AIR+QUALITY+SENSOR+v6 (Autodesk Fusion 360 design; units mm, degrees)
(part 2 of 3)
sketch "Sketch29" plane through (0, 1.3, 0) normal (0, 1, 0) x axis (-1, 0, 0)
  line L1 (13.75, -36.3) -> (13.75, 21.15)
  line L2 (15, -36.3) -> (13.75, -36.3)
  line L3 (23.8, 34.5) -> (23.8, -27.5)
  line L4 (18, 36.3) -> (22, 36.3)
  line L5 (18, 32.55) -> (18, 36.3)
  line L6 (13, 32.55) -> (18, 32.55)
  line L7 (13, 36.3) -> (13, 32.55)
  line L8 (-13, 36.3) -> (13, 36.3)
  line L9 (-13, 32.55) -> (-13, 36.3)
  line L10 (-18, 32.55) -> (-13, 32.55)
  line L11 (-18, 36.3) -> (-18, 32.55)
  line L12 (-22, 36.3) -> (-18, 36.3)
  line L13 (-23.8, -27.5) -> (-23.8, 34.5)
  line L14 (-13.75, -36.3) -> (-15, -36.3)
  line L15 (-13.75, 21.15) -> (-13.75, -36.3)
  line L16 (11.75, 23.15) -> (-11.75, 23.15)
  line L17 (-6, 25.9667) -> (6, 25.9667)
  line L18 (-6, 20.3333) -> (-6, 25.9667)
  line L19 (6, 20.3333) -> (-6, 20.3333)
  line L20 (6, 25.9667) -> (6, 20.3333)
  line L21 (-6, 20.3333) -> (6, 25.9667)
  line L22 (6, 20.3333) -> (-6, 25.9667)
  line L23 (-4, 25.9667) -> (4, 25.9667)
  line L24 (-4, 20.3333) -> (-4, 25.9667)
  line L25 (4, 20.3333) -> (-4, 20.3333)
  line L26 (4, 25.9667) -> (4, 20.3333)
  line L27 (-4, 20.3333) -> (4, 25.9667)
  line L28 (4, 20.3333) -> (-4, 25.9667)
  arc A1 centre (15, -27.5) radius 8.8 clockwise from (23.8, -27.5) to (15, -36.3)
  arc A2 centre (22, 34.5) radius 1.8 clockwise from (22, 36.3) to (23.8, 34.5)
  arc A3 centre (-22, 34.5) radius 1.8 clockwise from (-23.8, 34.5) to (-22, 36.3)
  arc A4 centre (-15, -27.5) radius 8.8 clockwise from (-15, -36.3) to (-23.8, -27.5)
  arc A5 centre (-11.75, 21.15) radius 2 clockwise from (-13.75, 21.15) to (-11.75, 23.15)
  arc A6 centre (11.75, 21.15) radius 2 clockwise from (11.75, 23.15) to (13.75, 21.15)
  point P34 (0, 23.15)
  point P39 (0, 23.15)
  point P35 (4, 25.9667)
  point P32 (-6, 20.3333)
  point P33 (6, 20.3333)
  horizontal L17
  perpendicular L17 L18
  parallel L17 L19
  parallel L18 L20
  coincident L21 P34
  coincident L22 P34
  midpoint L16 P34
  horizontal L23
  perpendicular L23 L24
  parallel L23 L25
  parallel L24 L26
  coincident L27 P39
  coincident L28 P39
  coincident L17 P35
  coincident P34 P39
  dimension "d189" distance P32 P33 = 12
  dimension "d190" distance L20 L26 = 2
extrude "Extrude35" new body sketch "Sketch29" profile of L16 L17 L18 L20 L24 L26 along normal blind 7
move_face "MoveFace16"
sketch "Sketch30" plane through (0, 0, 39.5) normal (0, 0, 1) x axis (-1, 0, 0)
  line L1 (10.8759, -1.8) -> (22, -1.8)
  line L2 (10.8759, -6.5) -> (10.8759, -1.8)
  curve K1 (10.2532, -7) -> (10.8759, -6.5)
  line L3 (9.0455, -7) -> (10.2532, -7)
  curve K2 (8.4566, -6.5) -> (9.0455, -7)
  line L4 (8.4566, -1.8) -> (8.4566, -6.5)
  line L5 (2.4622, -1.8) -> (8.4566, -1.8)
  line L6 (-22, -1.8) -> (-10.4622, -1.8)
  line L7 (-22, -25) -> (-22, -1.8)
  line L8 (22, -25) -> (-22, -25)
  line L9 (22, -1.8) -> (22, -25)
  line L10 (6.5, -12.5) -> (-4, -12.5)
  line L11 (-14.5, -12.5) -> (-4, -12.5)
  line L12 (-14.5, -26.2029) -> (-14.5, -12.5)
  line L13 (6.5, -27.3065) -> (6.5, -12.5)
  circle C1 centre (-4, -12.5) radius 10.5
  arc A1 centre (-4, -12.5) radius 12.5 clockwise from (-10.4622, -1.8) to (2.4622, -1.8)
  point P2 (-4, -12.5)
  point P15 (-4, -12.5)
  point P16 (6.5, -12.5)
  point P17 (-4, -12.5)
  point P18 (-14.5, -12.5)
  coincident P2 P15
  coincident C1 P16
  horizontal L10
  coincident P2 P17
  coincident C1 P18
  parallel L10 L11
  tangent C1 L12
  tangent C1 L13
extrude "Extrude36" cut sketch "Sketch30" profile of C1 L8 L12 L13 against normal blind 1.2
sketch "Sketch31" plane through (0, 1.3, 0) normal (0, 1, 0) x axis (-1, 0, 0)
  line L1 (13.75, -36.3) -> (13.75, 21.15)
  line L2 (15, -36.3) -> (13.75, -36.3)
  line L3 (23.8, 34.5) -> (23.8, -27.5)
  line L4 (18, 36.3) -> (22, 36.3)
  line L5 (18, 32.55) -> (18, 36.3)
  line L6 (13, 32.55) -> (18, 32.55)
  line L7 (13, 36.3) -> (13, 32.55)
  line L8 (-13, 36.3) -> (13, 36.3)
  line L9 (-13, 32.55) -> (-13, 36.3)
  line L10 (-18, 32.55) -> (-13, 32.55)
  line L11 (-18, 36.3) -> (-18, 32.55)
  line L12 (-22, 36.3) -> (-18, 36.3)
  line L13 (-23.8, -27.5) -> (-23.8, 34.5)
  line L14 (-13.75, -36.3) -> (-15, -36.3)
  line L15 (-13.75, 21.15) -> (-13.75, -36.3)
  line L16 (11.75, 23.15) -> (-11.75, 23.15)
  line L17 (16.2, 32.55) -> (16.2, 35.025)
  line L18 (18, 32.55) -> (16.2, 32.55)
  line L19 (18, 38.3) -> (18, 32.55)
  line L20 (14.2, 38.3) -> (18, 38.3)
  line L21 (14.2, 35.025) -> (14.2, 38.3)
  line L22 (16.2, 35.025) -> (14.2, 35.025)
  line L23 (14.2, 35.025) -> (16.2, 35.025)
  line L24 (14.2, 37.5) -> (14.2, 35.025)
  line L25 (13, 37.5) -> (14.2, 37.5)
  line L26 (13, 32.55) -> (13, 37.5)
  line L27 (16.2, 32.55) -> (13, 32.55)
  line L28 (16.2, 35.025) -> (16.2, 32.55)
  line L29 (-14.5, 38.3) -> (-14.5, 35.025)
  line L30 (-18, 38.3) -> (-14.5, 38.3)
  line L31 (-18, 32.55) -> (-18, 38.3)
  line L32 (-16.2, 32.55) -> (-18, 32.55)
  line L33 (-16.2, 35.025) -> (-16.2, 32.55)
  line L34 (-14.5, 35.025) -> (-16.2, 35.025)
  line L35 (-16, 34.6) -> (16, 34.6)
  line L36 (-16, 33.5) -> (-16, 34.6)
  line L37 (16, 33.5) -> (-16, 33.5)
  line L38 (16, 34.6) -> (16, 33.5)
  line L39 (10.4443, 34.05) -> (16, 34.05)
  line L40 (16.2, 33.075) -> (14.2, 33.075)
  line L41 (18, 33.075) -> (14.2, 33.075)
  line L42 (18, 31.075) -> (18, 33.075)
  line L43 (14.2, 31.075) -> (18, 31.075)
  line L44 (14.2, 33.075) -> (14.2, 31.075)
  arc A1 centre (15, -27.5) radius 8.8 clockwise from (23.8, -27.5) to (15, -36.3)
  arc A2 centre (22, 34.5) radius 1.8 clockwise from (22, 36.3) to (23.8, 34.5)
  arc A3 centre (-22, 34.5) radius 1.8 clockwise from (-23.8, 34.5) to (-22, 36.3)
  arc A4 centre (-15, -27.5) radius 8.8 clockwise from (-15, -36.3) to (-23.8, -27.5)
  arc A5 centre (-11.75, 21.15) radius 2 clockwise from (-13.75, 21.15) to (-11.75, 23.15)
  arc A6 centre (11.75, 21.15) radius 2 clockwise from (11.75, 23.15) to (13.75, 21.15)
  point P52 (16, 34.05)
  point P30 (16.2, 35.025)
  point P55 (16.2, 33.075)
  point P35 (14.2, 35.025)
  point P54 (14.2, 33.075)
  point P58 (14.2, 31.075)
  midpoint L38 P52
  horizontal L39
  symmetric P30 L39 P55
  symmetric P35 L39 P54
  horizontal L41
  vertical L42
  horizontal L43
  vertical L44
  dimension "d195" distance P54 P58 = 2
extrude "Extrude37" new body sketch "Sketch31" profile of L5 L6 L17 L18 L19 L27 L28 L40 L41 L42 L43 L44 along normal blind 21.2
mirror "Mirror3" mirrorStitchTolerance 0.1
move_face "MoveFace17"
combine "Combine11"
move_face "MoveFace18"
combine "Combine12"
move_face "MoveFace19"
remove_body "RemoveBody17"
sketch "Sketch32" plane through (0, 0, 38.1) normal (0, 0, 1) x axis (-1, 0, 0)
  line L1 (22, -25) -> (-22, -25)
  line L2 (22, -21) -> (22, -25)
  line L3 (-22, -21) -> (22, -21)
  line L4 (-22, -25) -> (-22, -21)
  line L5 (-14.5, -12.5) -> (-14.5, -25)
  line L6 (6.5, -25) -> (6.5, -12.5)
  line L7 (22, -25) -> (6.5, -25)
  line L8 (22, -1.8) -> (22, -25)
  line L9 (10.8759, -1.8) -> (22, -1.8)
  line L10 (10.8759, -6.5) -> (10.8759, -1.8)
  curve K1 (10.2532, -7) -> (10.8759, -6.5)
  line L11 (9.0455, -7) -> (10.2532, -7)
  curve K2 (8.4566, -6.5) -> (9.0455, -7)
  line L12 (8.4566, -1.8) -> (8.4566, -6.5)
  line L13 (2.4622, -1.8) -> (8.4566, -1.8)
  line L14 (-22, -1.8) -> (-10.4622, -1.8)
  line L15 (-22, -25) -> (-22, -1.8)
  line L16 (-14.5, -25) -> (-22, -25)
  arc A1 centre (-4, -12.5) radius 10.5 clockwise from (-14.5, -12.5) to (6.5, -12.5)
  arc A2 centre (-4, -12.5) radius 12.5 clockwise from (-10.4622, -1.8) to (2.4622, -1.8)
  circle C1 centre (-4, -12.5) radius 10.5
  point P7 (-14.5, -12.5)
  concentric A1 C1
  coincident P7 C1
extrude "Extrude38" new body sketch "Sketch32" profile of L1 L3 L5 L6 C1 against normal blind 1.5
fillet "Fillet7" radius 0.5
move_face "MoveFace20"
combine "Combine13"
delete_face "DeleteFace20"
move_face "MoveFace21"
split "Split2"
extrude "Extrude39" cut of existing geometry blind -1.5
extrude "Extrude40" cut of existing geometry blind -1.5
split "Split3"
split "Split4"
move_face "MoveFace22"
move_face "MoveFace23"
combine "Combine14"
delete_face "DeleteFace21"
delete_face "DeleteFace22"
sketch "Sketch33" plane through (0, -0.2, 0) normal (0, -1, 0) x axis (1, 0, 0)
  line L1 (-22, 37.5) -> (22, 37.5)
  line L2 (-25, -27.5) -> (-25, 34.5)
  line L3 (15, -37.5) -> (-15, -37.5)
  line L4 (25, 34.5) -> (25, -27.5)
  line L5 (-35.7104, 55.4052) -> (-22, 34.5)
  line L6 (-39.8914, 52.6631) -> (-35.7104, 55.4052)
  line L7 (-31.5293, 58.1472) -> (-35.7104, 55.4052)
  line L8 (-10, 37.5) -> (-22, 37.5)
  line L9 (-25, 19.5) -> (-25, 34.5)
  line L10 (-25, 19.5) -> (-39.8914, 52.6631)
  line L11 (-10, 37.5) -> (-31.5293, 58.1472)
  line L12 (-31.8817, 54.3285) -> (-34.0651, 52.8965)
  line L13 (-17.4624, 40.5) -> (-31.8817, 54.3285)
  line L14 (-17.4624, 40.5) -> (-22, 40.5)
  line L15 (-36.1065, 51.5577) -> (-34.0651, 52.8965)
  line L16 (-28, 33.5046) -> (-36.1065, 51.5577)
  line L17 (-28, 33.5046) -> (-28, 34.5)
  line L18 (15, -40.5) -> (-15, -40.5)
  line L19 (28, 34.5) -> (28, -27.5)
  line L20 (-22, 40.5) -> (22, 40.5)
  line L21 (-28, -27.5) -> (-28, 34.5)
  arc A1 centre (-22, 34.5) radius 3 clockwise from (-25, 34.5) to (-22, 37.5)
  arc A2 centre (-15, -27.5) radius 10 clockwise from (-15, -37.5) to (-25, -27.5)
  arc A3 centre (15, -27.5) radius 10 clockwise from (25, -27.5) to (15, -37.5)
  arc A4 centre (22, 34.5) radius 3 clockwise from (22, 37.5) to (25, 34.5)
  arc A5 centre (-15, -27.5) radius 13 clockwise from (-15, -40.5) to (-28, -27.5)
  arc A6 centre (15, -27.5) radius 13 clockwise from (28, -27.5) to (15, -40.5)
  arc A7 centre (22, 34.5) radius 6 clockwise from (22, 40.5) to (28, 34.5)
  arc A8 centre (-22, 34.5) radius 6 clockwise from (-28, 34.5) to (-22, 40.5)
  point P5 (-22, 34.5)
  point P14 (-22, 34.5)
  point P3 (-22, 37.5)
  point P18 (-22, 37.5)
  point P4 (-25, 34.5)
  point P20 (-25, 34.5)
  point P15 (-35.7104, 55.4052)
  point P16 (-39.8914, 52.6631)
  point P17 (-31.5293, 58.1472)
  point P19 (-10, 37.5)
  point P21 (-25, 19.5)
  coincident P5 P14
  perpendicular L5 L6
  perpendicular L5 L7
  coincident P3 P18
  parallel L1 L8
  coincident P4 P20
  parallel L2 L9
  dimension "d208" distance P14 P15 = 25
  dimension "d209" distance P15 P16 = 5
  dimension "d210" distance P15 P17 = 5
  dimension "d211" distance P18 P19 = 12
  dimension "d212" distance P20 P21 = 15
  dimension "d213" = 3
  dimension "d214" = -3
  dimension "d215" = 3
extrude "Extrude41" new body sketch "Sketch33" profile of L1 A1 L2 L5 L6 L7 L8 L9 L10 L11 L12 L13 L14 L15 L16 L17 A8 L20 L21 against normal blind 4
offset_faces "OffsetFaces10" distance -0.5
fillet "Fillet8" radius 2.5
combine "Combine15"
offset_faces "OffsetFaces11" distance -0.5
fillet "Fillet9" radius 1.25
fillet "Fillet10" radius 5
sketch "Sketch34" plane through (0, 31, 0) normal (0, 1, 0) x axis (-1, 0, 0)
  line L1 (-1.5, -10.5) -> (-14.5, -10.5)
  line L2 (-1.5, -30.5) -> (-1.5, -10.5)
  line L3 (-14.5, -30.5) -> (-1.5, -30.5)
  line L4 (-14.5, -10.5) -> (-14.5, -30.5)
  line L5 (-14.975, -30.405) -> (-14.975, -10.595)
  line L6 (-1.025, -30.405) -> (-14.975, -30.405)
  line L7 (-1.025, -10.595) -> (-1.025, -30.405)
  line L8 (-14.975, -10.595) -> (-1.025, -10.595)
  line L9 (-12.2, -27.65) -> (-3.8, -27.65)
  curve K1 (-12.2, -27.65) -> (-12.9, -26.8848)
  line L10 (-12.9, -17.1081) -> (-12.9, -26.8848)
  curve K2 (-12.9, -17.1081) -> (-12.2, -13.35)
  line L11 (-3.8, -13.35) -> (-12.2, -13.35)
  curve K3 (-3.8, -13.35) -> (-3.1, -17.1081)
  line L12 (-3.1, -26.8848) -> (-3.1, -17.1081)
  curve K4 (-3.1, -26.8848) -> (-3.8, -27.65)
  line L13 (0.575, -32.005) -> (-16.575, -32.005)
  line L14 (0.575, -8.995) -> (0.575, -32.005)
  line L15 (-16.575, -8.995) -> (0.575, -8.995)
  line L16 (-16.575, -32.005) -> (-16.575, -8.995)
  circle C1 centre (-8, -20.5) radius 15.3744
  dimension "d226" = 1.6
extrude "Extrude42" add sketch "Sketch34" profile of C1 L15 L13 L14 L16 along normal blind 2
delete_face "DeleteFace23"
offset_faces "OffsetFaces12" distance 0.5
fillet "Fillet11" radius 1
delete_face "DeleteFace24"
position "Position15"
sketch "Sketch35" plane through (27, 0, 0) normal (1, 0, 0) x axis (0, 1, 0)
  line L1 (22.4, -17.1667) -> (22.4, -13.1667)
  line L2 (4.4, -17.1667) -> (22.4, -17.1667)
  line L3 (4.4, -13.1667) -> (4.4, -17.1667)
  line L4 (22.4, -13.1667) -> (4.4, -13.1667)
  line L5 (22.4, -26.5) -> (22.4, -22.5)
  line L6 (4.4, -26.5) -> (22.4, -26.5)
  line L7 (4.4, -22.5) -> (4.4, -26.5)
  line L8 (22.4, -22.5) -> (4.4, -22.5)
  line L9 (22.4, -7.8333) -> (22.4, -3.8333)
  line L10 (4.4, -7.8333) -> (22.4, -7.8333)
  line L11 (4.4, -3.8333) -> (4.4, -7.8333)
  line L12 (22.4, -3.8333) -> (4.4, -3.8333)
  line L13 (1.8, -27.5) -> (1.8, 34.5)
  line L14 (25, -27.5) -> (1.8, -27.5)
  line L15 (25, 34.5) -> (25, -27.5)
  line L16 (1.8, 34.5) -> (25, 34.5)
  line L17 (7.175, 6.595) -> (7.175, 26.405)
  line L18 (21.125, 6.595) -> (7.175, 6.595)
  line L19 (21.125, 26.405) -> (21.125, 6.595)
  line L20 (7.175, 26.405) -> (21.125, 26.405)
  line L21 (9.95, 9.35) -> (18.35, 9.35)
  curve K1 (9.95, 9.35) -> (9.25, 10.1152)
  line L22 (9.25, 19.8919) -> (9.25, 10.1152)
  curve K2 (9.25, 19.8919) -> (9.95, 23.65)
  line L23 (18.35, 23.65) -> (9.95, 23.65)
  curve K3 (18.35, 23.65) -> (19.05, 19.8919)
  line L24 (19.05, 10.1152) -> (19.05, 19.8919)
  curve K4 (19.05, 10.1152) -> (18.35, 9.35)
  line L25 (21.125, 6.595) -> (7.175, 26.405)
  line L26 (3.3, 32) -> (25, 32)
  line L27 (3.3, 1) -> (3.3, 32)
  line L28 (25, 1) -> (3.3, 1)
  line L29 (25, 32) -> (25, 1)
  line L30 (3.3, 1) -> (25, 32)
  line L31 (25, 1) -> (3.3, 32)
  point P18 (7.175, 26.405)
  point P30 (7.175, 26.405)
  point P20 (21.125, 6.595)
  point P31 (21.125, 6.595)
  point P36 (14.15, 16.5)
  point P33 (3.3, 32)
  point P34 (3.3, 1)
  coincident P18 P30
  coincident P20 P31
  horizontal L26
  perpendicular L26 L27
  parallel L26 L28
  parallel L27 L29
  coincident L30 P36
  coincident L31 P36
  midpoint L25 P36
  dimension "d232" distance P33 P34 = 31
extrude "Extrude43" new body sketch "Sketch35" profile of L15 L17 L18 L19 L20 L21 K1 L22 K2 L23 K3 L24 K4 L25 L26 L27 L28 L29 along normal blind 5.7
offset_faces "OffsetFaces13" distance -2
draft "Draft3" Angle1 30 Angle2 0
shell "Shell4" innerThickness 1.2
extrude "Extrude44" cut of existing geometry blind -6
combine "Combine16"
delete_face "DeleteFace25"
extrude "Extrude45" cut of existing geometry blind -2
move_face "MoveFace24"
position "Position16"
sketch "Sketch36" plane through (32.7, 0, 0) normal (1, 0, 0) x axis (0, 1, 0)
  line L1 (25, 30) -> (25, 3)
  line L2 (5.3, 30) -> (25, 30)
  line L3 (5.3, 3) -> (5.3, 30)
  line L4 (25, 3) -> (5.3, 3)
  line L5 (8.175, 6.595) -> (8.175, 26.405)
  line L6 (22.125, 26.405) -> (22.125, 6.595)
  line L7 (10.95, 9.35) -> (19.35, 9.35)
  curve K1 (10.95, 9.35) -> (10.25, 10.1152)
  line L8 (10.25, 19.8919) -> (10.25, 10.1152)
  curve K2 (10.25, 19.8919) -> (10.95, 23.65)
  line L9 (19.35, 23.65) -> (10.95, 23.65)
  curve K3 (19.35, 23.65) -> (20.05, 19.8919)
  line L10 (20.05, 10.1152) -> (20.05, 19.8919)
  curve K4 (20.05, 10.1152) -> (19.35, 9.35)
  line L11 (22.125, 6.595) -> (8.175, 26.405)
  line L12 (8.65, 26.5) -> (21.65, 26.5)
  line L13 (8.65, 6.5) -> (8.65, 26.5)
  line L14 (21.65, 6.5) -> (8.65, 6.5)
  line L15 (21.65, 26.5) -> (21.65, 6.5)
  line L16 (8.65, 6.5) -> (21.65, 26.5)
  line L17 (21.65, 6.5) -> (8.65, 26.5)
  point P6 (8.175, 26.405)
  point P18 (8.175, 26.405)
  point P8 (22.125, 6.595)
  point P19 (22.125, 6.595)
  point P24 (15.15, 16.5)
  point P22 (8.65, 6.5)
  point P23 (21.65, 6.5)
  point P21 (8.65, 26.5)
  coincident P6 P18
  coincident P8 P19
  horizontal L12
  perpendicular L12 L13
  parallel L12 L14
  parallel L13 L15
  coincident L16 P24
  coincident L17 P24
  midpoint L11 P24
  dimension "d243" distance P22 P23 = 13
  dimension "d244" distance P21 P22 = 20
extrude "Extrude46" cut sketch "Sketch36" profile of L7 K1 L8 K2 L9 K3 L10 K4 L11 L12 L13 L14 L15 against normal blind 1.2
extrude "Extrude47" cut of existing geometry blind -7
sketch "Sketch37" plane through (0, 27, 0) normal (0, 1, 0) x axis (-1, 0, 0)
  line L1 (-13.5, -2.6142) -> (13.5, -2.6142)
  line L2 (-23.2642, 26.15) -> (-23.2642, 7.15)
  line L3 (13.5, 35.9142) -> (-13.5, 35.9142)
  line L4 (23.2642, 7.15) -> (23.2642, 26.15)
  line L5 (27, 34.5) -> (27, -27.5)
  line L6 (-22, 39.5) -> (22, 39.5)
  line L7 (-27, -27.5) -> (-27, 34.5)
  line L8 (15, -39.5) -> (-15, -39.5)
  line L9 (-31.5, 26.5) -> (-32.7, 26.5)
  line L10 (-31.5, 29.3072) -> (-31.5, 26.5)
  line L11 (-27, 31.9053) -> (-31.5, 29.3072)
  line L12 (-25.8, 31.9053) -> (-27, 31.9053)
  line L13 (-25.8, 34.5) -> (-25.8, 31.9053)
  line L14 (-14.5, 38.3) -> (-22, 38.3)
  line L15 (-14.5, 39.5) -> (-14.5, 38.3)
  line L16 (-22, 39.5) -> (-14.5, 39.5)
  line L17 (-27, 33.2909) -> (-27, 34.5)
  line L18 (-32.7, 30) -> (-27, 33.2909)
  line L19 (-32.7, 26.5) -> (-32.7, 30)
  line L20 (-32.7, 6.5) -> (-31.5, 6.5)
  line L21 (-32.7, 3) -> (-32.7, 6.5)
  line L22 (-27, -0.2909) -> (-32.7, 3)
  line L23 (-27, -27.5) -> (-27, -0.2909)
  line L24 (15, -39.5) -> (-15, -39.5)
  line L25 (27, 34.5) -> (27, -27.5)
  line L26 (6.5, 39.5) -> (22, 39.5)
  line L27 (6.5, 38.3) -> (6.5, 39.5)
  line L28 (22, 38.3) -> (6.5, 38.3)
  line L29 (25.8, -27.5) -> (25.8, 34.5)
  line L30 (-15, -38.3) -> (15, -38.3)
  line L31 (-25.8, 1.0947) -> (-25.8, -27.5)
  line L32 (-27, 1.0947) -> (-25.8, 1.0947)
  line L33 (-31.5, 3.6928) -> (-27, 1.0947)
  line L34 (-31.5, 6.5) -> (-31.5, 3.6928)
  line L35 (-32.7, 6.5) -> (-32.7, 26.5)
  arc A1 centre (13.5, 7.15) radius 9.7642 clockwise from (23.2642, 7.15) to (13.5, -2.6142)
  arc A2 centre (-13.5, 7.15) radius 9.7642 clockwise from (-13.5, -2.6142) to (-23.2642, 7.15)
  arc A3 centre (-13.5, 26.15) radius 9.7642 clockwise from (-23.2642, 26.15) to (-13.5, 35.9142)
  arc A4 centre (13.5, 26.15) radius 9.7642 clockwise from (13.5, 35.9142) to (23.2642, 26.15)
  arc A5 centre (15, -27.5) radius 12 clockwise from (27, -27.5) to (15, -39.5)
  arc A6 centre (22, 34.5) radius 5 clockwise from (22, 39.5) to (27, 34.5)
  arc A7 centre (-22, 34.5) radius 5 clockwise from (-27, 34.5) to (-22, 39.5)
  arc A8 centre (-15, -27.5) radius 12 clockwise from (-15, -39.5) to (-27, -27.5)
  circle C1 centre (-8, -20.5) radius 16.9638
  arc A9 centre (-22, 34.5) radius 3.8 clockwise from (-25.8, 34.5) to (-22, 38.3)
  arc A10 centre (-22, 34.5) radius 5 clockwise from (-27, 34.5) to (-22, 39.5)
  arc A11 centre (-15, -27.5) radius 12 clockwise from (-15, -39.5) to (-27, -27.5)
  arc A12 centre (15, -27.5) radius 12 clockwise from (27, -27.5) to (15, -39.5)
  arc A13 centre (22, 34.5) radius 5 clockwise from (22, 39.5) to (27, 34.5)
  arc A14 centre (22, 34.5) radius 3.8 clockwise from (22, 38.3) to (25.8, 34.5)
  arc A15 centre (15, -27.5) radius 10.8 clockwise from (25.8, -27.5) to (15, -38.3)
  arc A16 centre (-15, -27.5) radius 10.8 clockwise from (-15, -38.3) to (-25.8, -27.5)
  point P27 (-32.7, 26.5)
  point P65 (-32.7, 26.5)
  point P42 (-32.7, 6.5)
  point P66 (-32.7, 6.5)
  coincident P27 P65
  coincident P42 P66
extrude "Extrude48" new body sketch "Sketch37" profile of L7 L9 L10 L11 L18 L19 L20 L21 L22 L33 L34 L35 against normal blind 2
sketch "Sketch38" plane through (0, 27, 0) normal (0, 1, 0) x axis (-1, 0, 0)
  line L1 (-32.7, 30) -> (-27, 33.2909)
  line L2 (-32.7, 3) -> (-32.7, 30)
  line L3 (-27, -0.2909) -> (-32.7, 3)
  line L4 (-27, 33.2909) -> (-27, -0.2909)
  line L5 (-32.7, 6.5) -> (-31.5, 6.5)
  line L6 (-32.7, 3) -> (-32.7, 6.5)
  line L7 (-27, -0.2909) -> (-32.7, 3)
  line L8 (-27, -27.5) -> (-27, -0.2909)
  line L9 (15, -39.5) -> (-15, -39.5)
  line L10 (27, 34.5) -> (27, -27.5)
  line L11 (6.5, 39.5) -> (22, 39.5)
  line L12 (6.5, 38.3) -> (6.5, 39.5)
  line L13 (22, 38.3) -> (6.5, 38.3)
  line L14 (25.8, -27.5) -> (25.8, 34.5)
  line L15 (-15, -38.3) -> (15, -38.3)
  line L16 (-25.8, 1.0947) -> (-25.8, -27.5)
  line L17 (-27, 1.0947) -> (-25.8, 1.0947)
  line L18 (-31.5, 3.6928) -> (-27, 1.0947)
  line L19 (-31.5, 6.5) -> (-31.5, 3.6928)
  line L20 (-31.5, 26.5) -> (-32.7, 26.5)
  line L21 (-31.5, 29.3072) -> (-31.5, 26.5)
  line L22 (-27, 31.9053) -> (-31.5, 29.3072)
  line L23 (-25.8, 31.9053) -> (-27, 31.9053)
  line L24 (-25.8, 34.5) -> (-25.8, 31.9053)
  line L25 (-14.5, 38.3) -> (-22, 38.3)
  line L26 (-14.5, 39.5) -> (-14.5, 38.3)
  line L27 (-22, 39.5) -> (-14.5, 39.5)
  line L28 (-27, 33.2909) -> (-27, 34.5)
  line L29 (-32.7, 30) -> (-27, 33.2909)
  line L30 (-32.7, 26.5) -> (-32.7, 30)
  line L31 (-31.5, 26.5) -> (-32.7, 26.5)
  line L32 (-31.5, 6.5) -> (-31.5, 26.5)
  line L33 (-32.7, 6.5) -> (-31.5, 6.5)
  line L34 (-32.7, 26.5) -> (-32.7, 6.5)
  arc A1 centre (-15, -27.5) radius 12 clockwise from (-15, -39.5) to (-27, -27.5)
  arc A2 centre (15, -27.5) radius 12 clockwise from (27, -27.5) to (15, -39.5)
  arc A3 centre (22, 34.5) radius 5 clockwise from (22, 39.5) to (27, 34.5)
  arc A4 centre (22, 34.5) radius 3.8 clockwise from (22, 38.3) to (25.8, 34.5)
  arc A5 centre (15, -27.5) radius 10.8 clockwise from (25.8, -27.5) to (15, -38.3)
  arc A6 centre (-15, -27.5) radius 10.8 clockwise from (-15, -38.3) to (-25.8, -27.5)
  arc A7 centre (-22, 34.5) radius 3.8 clockwise from (-25.8, 34.5) to (-22, 38.3)
  arc A8 centre (-22, 34.5) radius 5 clockwise from (-27, 34.5) to (-22, 39.5)
  point P6 (-31.5, 6.5)
  point P46 (-31.5, 6.5)
  point P30 (-32.7, 26.5)
  point P44 (-32.7, 26.5)
  horizontal L31
  vertical L32
  horizontal L33
  vertical L34
  coincident P6 P46
  coincident P30 P44
extrude "Extrude49" new body sketch "Sketch38" profile of L2 L5 L20 L31 L32 L33 L34 against normal blind 5
combine "Combine17"
sketch "Sketch39" plane through (0, 25, 0) normal (0, 1, 0) x axis (-1, 0, 0)
  line L1 (-32.7, 6.5) -> (-31.5, 6.5)
  line L2 (-32.7, 3) -> (-32.7, 6.5)
  line L3 (-27, -0.2909) -> (-32.7, 3)
  line L4 (-27, -27.5) -> (-27, -0.2909)
  line L5 (15, -39.5) -> (-15, -39.5)
  line L6 (27, 34.5) -> (27, -27.5)
  line L7 (6.5, 39.5) -> (22, 39.5)
  line L8 (6.5, 38.3) -> (6.5, 39.5)
  line L9 (22, 38.3) -> (6.5, 38.3)
  line L10 (25.8, -27.5) -> (25.8, 34.5)
  line L11 (-15, -38.3) -> (15, -38.3)
  line L12 (-25.8, 1.0947) -> (-25.8, -27.5)
  line L13 (-27, 1.0947) -> (-25.8, 1.0947)
  line L14 (-31.5, 3.6928) -> (-27, 1.0947)
  line L15 (-31.5, 6.5) -> (-31.5, 3.6928)
  line L16 (-31.5, 26.5) -> (-32.7, 26.5)
  line L17 (-31.5, 29.3072) -> (-31.5, 26.5)
  line L18 (-27, 31.9053) -> (-31.5, 29.3072)
  line L19 (-25.8, 31.9053) -> (-27, 31.9053)
  line L20 (-25.8, 34.5) -> (-25.8, 31.9053)
  line L21 (-14.5, 38.3) -> (-22, 38.3)
  line L22 (-14.5, 39.5) -> (-14.5, 38.3)
  line L23 (-22, 39.5) -> (-14.5, 39.5)
  line L24 (-27, 33.2909) -> (-27, 34.5)
  line L25 (-32.7, 30) -> (-27, 33.2909)
  line L26 (-32.7, 26.5) -> (-32.7, 30)
  line L27 (-31.3, 6.7) -> (-31.3, 3.8083)
  line L28 (-32.9, 6.7) -> (-31.3, 6.7)
  line L29 (-32.9, 2.8845) -> (-32.9, 6.7)
  line L30 (-27.2, -0.4064) -> (-32.9, 2.8845)
  line L31 (-27.2, -27.5) -> (-27.2, -0.4064)
  line L32 (15, -39.7) -> (-15, -39.7)
  line L33 (27.2, 34.5) -> (27.2, -27.5)
  line L34 (6.3, 39.7) -> (22, 39.7)
  line L35 (6.3, 38.1) -> (6.3, 39.7)
  line L36 (22, 38.1) -> (6.3, 38.1)
  line L37 (25.6, -27.5) -> (25.6, 34.5)
  line L38 (-15, -38.1) -> (15, -38.1)
  line L39 (-25.6, 1.2947) -> (-25.6, -27.5)
  line L40 (-26.9464, 1.2947) -> (-25.6, 1.2947)
  line L41 (-31.3, 3.8083) -> (-26.9464, 1.2947)
  line L42 (-25.6, 31.7053) -> (-26.9464, 31.7053)
  line L43 (-25.6, 34.5) -> (-25.6, 31.7053)
  line L44 (-14.3, 38.1) -> (-22, 38.1)
  line L45 (-14.3, 39.7) -> (-14.3, 38.1)
  line L46 (-22, 39.7) -> (-14.3, 39.7)
  line L47 (-27.2, 33.4064) -> (-27.2, 34.5)
  line L48 (-32.9, 30.1155) -> (-27.2, 33.4064)
  line L49 (-32.9, 26.3) -> (-32.9, 30.1155)
  line L50 (-31.3, 26.3) -> (-32.9, 26.3)
  line L51 (-31.3, 29.1917) -> (-31.3, 26.3)
  line L52 (-26.9464, 31.7053) -> (-31.3, 29.1917)
  line L53 (-34.4, 8.2) -> (-29.8, 8.2)
  line L54 (-34.4, 2.0185) -> (-34.4, 8.2)
  line L55 (-28.7, -1.2724) -> (-34.4, 2.0185)
  line L56 (-28.7, -27.5) -> (-28.7, -1.2724)
  line L57 (15, -41.2) -> (-15, -41.2)
  line L58 (28.7, 34.5) -> (28.7, -27.5)
  line L59 (4.8, 41.2) -> (22, 41.2)
  line L60 (4.8, 36.6) -> (4.8, 41.2)
  line L61 (22, 36.6) -> (4.8, 36.6)
  line L62 (24.1, -27.5) -> (24.1, 34.5)
  line L63 (-15, -36.6) -> (15, -36.6)
  line L64 (-24.1, 2.7947) -> (-24.1, -27.5)
  line L65 (-26.5445, 2.7947) -> (-24.1, 2.7947)
  line L66 (-29.8, 4.6743) -> (-26.5445, 2.7947)
  line L67 (-29.8, 8.2) -> (-29.8, 4.6743)
  line L68 (-24.1, 34.5) -> (-24.1, 30.2053)
  line L69 (-12.8, 36.6) -> (-22, 36.6)
  line L70 (-12.8, 41.2) -> (-12.8, 36.6)
  line L71 (-22, 41.2) -> (-12.8, 41.2)
  line L72 (-28.7, 34.2724) -> (-28.7, 34.5)
  line L73 (-34.4, 30.9815) -> (-28.7, 34.2724)
  line L74 (-34.4, 24.8) -> (-34.4, 30.9815)
  line L75 (-29.8, 24.8) -> (-34.4, 24.8)
  line L76 (-29.8, 28.3257) -> (-29.8, 24.8)
  line L77 (-26.5445, 30.2053) -> (-29.8, 28.3257)
  line L78 (-24.1, 30.2053) -> (-26.5445, 30.2053)
  line L79 (-29.8, 24.8) -> (-29.8, 8.2)
  line L80 (-32.7, 6.5) -> (-31.5, 6.5)
  line L81 (-32.7, 26.5) -> (-32.7, 6.5)
  line L82 (-31.5, 26.5) -> (-32.7, 26.5)
  line L83 (-31.5, 6.5) -> (-31.5, 26.5)
  line L84 (-24.1, 31.7053) -> (-25.6, 31.7053)
  line L85 (-24.1, 1.2947) -> (-25.6, 1.2947)
  arc A1 centre (-15, -27.5) radius 12 clockwise from (-15, -39.5) to (-27, -27.5)
  arc A2 centre (15, -27.5) radius 12 clockwise from (27, -27.5) to (15, -39.5)
  arc A3 centre (22, 34.5) radius 5 clockwise from (22, 39.5) to (27, 34.5)
  arc A4 centre (22, 34.5) radius 3.8 clockwise from (22, 38.3) to (25.8, 34.5)
  arc A5 centre (15, -27.5) radius 10.8 clockwise from (25.8, -27.5) to (15, -38.3)
  arc A6 centre (-15, -27.5) radius 10.8 clockwise from (-15, -38.3) to (-25.8, -27.5)
  arc A7 centre (-22, 34.5) radius 3.8 clockwise from (-25.8, 34.5) to (-22, 38.3)
  arc A8 centre (-22, 34.5) radius 5 clockwise from (-27, 34.5) to (-22, 39.5)
  arc A9 centre (-15, -27.5) radius 12.2 clockwise from (-15, -39.7) to (-27.2, -27.5)
  arc A10 centre (15, -27.5) radius 12.2 clockwise from (27.2, -27.5) to (15, -39.7)
  arc A11 centre (22, 34.5) radius 5.2 clockwise from (22, 39.7) to (27.2, 34.5)
  arc A12 centre (22, 34.5) radius 3.6 clockwise from (22, 38.1) to (25.6, 34.5)
  arc A13 centre (15, -27.5) radius 10.6 clockwise from (25.6, -27.5) to (15, -38.1)
  arc A14 centre (-15, -27.5) radius 10.6 clockwise from (-15, -38.1) to (-25.6, -27.5)
  arc A15 centre (-22, 34.5) radius 3.6 clockwise from (-25.6, 34.5) to (-22, 38.1)
  arc A16 centre (-22, 34.5) radius 5.2 clockwise from (-27.2, 34.5) to (-22, 39.7)
  arc A17 centre (-15, -27.5) radius 13.7 clockwise from (-15, -41.2) to (-28.7, -27.5)
  arc A18 centre (15, -27.5) radius 13.7 clockwise from (28.7, -27.5) to (15, -41.2)
  arc A19 centre (22, 34.5) radius 6.7 clockwise from (22, 41.2) to (28.7, 34.5)
  arc A20 centre (22, 34.5) radius 2.1 clockwise from (22, 36.6) to (24.1, 34.5)
  arc A21 centre (15, -27.5) radius 9.1 clockwise from (24.1, -27.5) to (15, -36.6)
  arc A22 centre (-15, -27.5) radius 9.1 clockwise from (-15, -36.6) to (-24.1, -27.5)
  arc A23 centre (-22, 34.5) radius 2.1 clockwise from (-24.1, 34.5) to (-22, 36.6)
  arc A24 centre (-22, 34.5) radius 6.7 clockwise from (-28.7, 34.5) to (-22, 41.2)
  point P128 (-24.1, 31.7053)
  point P129 (-24.1, 1.2947)
  perpendicular L75 L79
  coincident L68 P128
  perpendicular L68 L84
  coincident L64 P129
  perpendicular L64 L85
  dimension "d253" = 0.2
  dimension "d254" = 0.2
  dimension "d255" = 1.7
  dimension "d256" = 1.7
extrude "Extrude50" new body sketch "Sketch39" profile of L27 L28 L40 L41 L42 L50 L51 L52 L53 L64 L65 L66 L67 L68 L75 L76 L77 L78 L79 L83 L84 L85 against normal blind 3
extrude "Extrude51" cut of existing geometry blind -0.2
extrude "Extrude52" cut of existing geometry blind -0.2
combine "Combine18"
split "Split5"
split "Split6"
move_face "MoveFace25"
combine "Combine19"
delete_face "DeleteFace26"
delete_face "DeleteFace27"
delete_face "DeleteFace28"
split "Split7"
remove_body "RemoveBody18"
combine "Combine20"
fillet "Fillet12" radius 4
delete_face "DeleteFace29"
component_from_bodies "Body->Comp1"
component_from_bodies "Body->Comp2"
sketch "Sketch40" plane through (0, 27, 0) normal (0, 1, 0) x axis (-1, 0, 0)
  line L1 (13.5, 35.9142) -> (-13.5, 35.9142)
  line L2 (23.2642, 7.15) -> (23.2642, 26.15)
  line L3 (-13.5, -2.6142) -> (13.5, -2.6142)
  line L4 (-23.2642, 26.15) -> (-23.2642, 7.15)
  line L5 (-32.7, 30) -> (-27, 33.2909)
  line L6 (-32.7, 3) -> (-32.7, 30)
  line L7 (-27, -0.2909) -> (-32.7, 3)
  line L8 (-27, -27.5) -> (-27, -0.2909)
  line L9 (15, -39.5) -> (-15, -39.5)
  line L10 (27, 34.5) -> (27, -27.5)
  line L11 (-22, 39.5) -> (22, 39.5)
  line L12 (-27, 33.2909) -> (-27, 34.5)
  line L13 (0, -9.5) -> (0, -39.5)
  line L14 (-27, -9.5) -> (0, -9.5)
  line L15 (27, -9.5) -> (0, -9.5)
  line L16 (-27, -24.5) -> (0, -24.5)
  line L17 (27, -24.5) -> (0, -24.5)
  line L18 (11.5, -14.5) -> (15.5, -14.5)
  line L19 (11.5, -34.5) -> (11.5, -14.5)
  line L20 (15.5, -34.5) -> (11.5, -34.5)
  line L21 (15.5, -14.5) -> (15.5, -34.5)
  line L22 (11.5, -34.5) -> (15.5, -14.5)
  line L23 (15.5, -34.5) -> (11.5, -14.5)
  line L24 (3.5, -22.5) -> (23.5, -22.5)
  line L25 (3.5, -26.5) -> (3.5, -22.5)
  line L26 (23.5, -26.5) -> (3.5, -26.5)
  line L27 (23.5, -22.5) -> (23.5, -26.5)
  line L28 (3.5, -26.5) -> (23.5, -22.5)
  line L29 (23.5, -26.5) -> (3.5, -22.5)
  arc A1 centre (13.5, 26.15) radius 9.7642 clockwise from (13.5, 35.9142) to (23.2642, 26.15)
  arc A2 centre (13.5, 7.15) radius 9.7642 clockwise from (23.2642, 7.15) to (13.5, -2.6142)
  arc A3 centre (-13.5, 7.15) radius 9.7642 clockwise from (-13.5, -2.6142) to (-23.2642, 7.15)
  arc A4 centre (-13.5, 26.15) radius 9.7642 clockwise from (-23.2642, 26.15) to (-13.5, 35.9142)
  arc A5 centre (-15, -27.5) radius 12 clockwise from (-15, -39.5) to (-27, -27.5)
  arc A6 centre (15, -27.5) radius 12 clockwise from (27, -27.5) to (15, -39.5)
  arc A7 centre (22, 34.5) radius 5 clockwise from (22, 39.5) to (27, 34.5)
  arc A8 centre (-22, 34.5) radius 5 clockwise from (-27, 34.5) to (-22, 39.5)
  circle C1 centre (-13.5, -24.5) radius 9.5
  circle C2 centre (-13.5, -24.5) radius 6
  point P30 (0, -39.5)
  point P32 (-27, -9.5)
  point P33 (27, -9.5)
  point P34 (0, -24.5)
  point P35 (-27, -24.5)
  point P36 (-13.5, -24.5)
  point P38 (27, -24.5)
  point P43 (13.5, -24.5)
  point P48 (13.5, -24.5)
  point P31 (0, -9.5)
  point P41 (11.5, -34.5)
  point P42 (15.5, -34.5)
  point P40 (11.5, -14.5)
  point P46 (3.5, -26.5)
  point P47 (23.5, -26.5)
  point P45 (3.5, -22.5)
  midpoint L9 P30
  perpendicular L9 L13
  coincident L8 P32
  perpendicular L8 L14
  coincident L10 P33
  perpendicular L10 L15
  midpoint L13 P34
  coincident L8 P35
  perpendicular L8 L16
  midpoint L16 P36
  concentric C1 C2
  coincident L10 P38
  perpendicular L10 L17
  horizontal L18
  perpendicular L18 L19
  parallel L18 L20
  parallel L19 L21
  coincident L22 P43
  coincident L23 P43
  midpoint L17 P43
  horizontal L24
  perpendicular L24 L25
  parallel L24 L26
  parallel L25 L27
  coincident L28 P48
  coincident L29 P48
  coincident P43 P48
  dimension "d265" distance P30 P31 = 30
  dimension "d266" diameter C1 = 19
  dimension "d267" diameter C2 = 12
  dimension "d268" distance P41 P42 = 4
  dimension "d269" distance P40 P41 = 20
  dimension "d270" distance P46 P47 = 20
  dimension "d271" distance P45 P46 = 4
extrude "Extrude53" new body sketch "Sketch40" profile of C1 C2 L18 L19 L20 L21 L24 L25 L26 L27 along normal blind 3
move "Move3"
move_face "MoveFace26"
fillet "Fillet13" radius 1
sketch "Sketch41" plane through (0, 0, 0) normal (0, 0, 1) x axis (1, 0, 0)
  circle C1 centre (-55.6251, 26.5608) radius 7.6
  dimension "d276" diameter C1 = 15.2
extrude "Extrude54" new body sketch "Sketch41" distance 25
fillet "Fillet14" radius 1
move "Move4"
move "Move5"
move "Move6"
move_face "MoveFace1"
move_face "MoveFace2"
sketch "Sketch42" plane through (0, 1.3, 0) normal (0, 1, 0) x axis (-1, 0, 0)
  line L1 (-6, 23.15) -> (-11.75, 23.15)
  line L2 (-6, 25.9667) -> (-6, 23.15)
  line L3 (-4, 25.9667) -> (-6, 25.9667)
  line L4 (-4, 23.15) -> (-4, 25.9667)
  line L5 (4, 23.15) -> (-4, 23.15)
  line L6 (4, 25.9667) -> (4, 23.15)
  line L7 (6, 25.9667) -> (4, 25.9667)
  line L8 (6, 23.15) -> (6, 25.9667)
  line L9 (11.75, 23.15) -> (6, 23.15)
  line L10 (13.75, 16.425) -> (13.75, 21.15)
  line L11 (23.8, 16.425) -> (13.75, 16.425)
  line L12 (23.8, 34.5) -> (23.8, 16.425)
  line L13 (19, 36.3) -> (22, 36.3)
  line L14 (19, 31.075) -> (19, 36.3)
  line L15 (14.2, 31.075) -> (19, 31.075)
  line L16 (14.2, 32.55) -> (14.2, 31.075)
  line L17 (13, 32.55) -> (14.2, 32.55)
  line L18 (13, 36.3) -> (13, 32.55)
  line L19 (-13, 36.3) -> (13, 36.3)
  line L20 (-13, 32.55) -> (-13, 36.3)
  line L21 (-14.7, 32.55) -> (-13, 32.55)
  line L22 (-14.7, 31.075) -> (-14.7, 32.55)
  line L23 (-19, 31.075) -> (-14.7, 31.075)
  line L24 (-19, 36.3) -> (-19, 31.075)
  line L25 (-22, 36.3) -> (-19, 36.3)
  line L26 (-23.8, -5.575) -> (-23.8, 34.5)
  line L27 (-13.75, -5.575) -> (-23.8, -5.575)
  line L28 (-13.75, 21.15) -> (-13.75, -5.575)
  line L29 (10.4, 21.5) -> (25.6, 21.5)
  line L30 (24.6, 22.5) -> (11.4, 22.5)
  line L31 (18, 22.7) -> (18, 22.5)
  line L32 (27.6856, 22.7) -> (18, 22.7)
  line L33 (12, 22.7) -> (18, 22.7)
  line L34 (30.5634, 22.7) -> (12, 22.7)
  line L35 (30.5634, 24.7) -> (30.5634, 22.7)
  line L36 (12, 24.7) -> (30.5634, 24.7)
  line L37 (12, 22.7) -> (12, 24.7)
  arc A1 centre (-11.75, 21.15) radius 2 clockwise from (-13.75, 21.15) to (-11.75, 23.15)
  arc A2 centre (11.75, 21.15) radius 2 clockwise from (11.75, 23.15) to (13.75, 21.15)
  arc A3 centre (22, 34.5) radius 1.8 clockwise from (22, 36.3) to (23.8, 34.5)
  arc A4 centre (-22, 34.5) radius 1.8 clockwise from (-23.8, 34.5) to (-22, 36.3)
  point P42 (18, 22.5)
  point P43 (18, 22.7)
  point P45 (12, 22.7)
  point P48 (12, 24.7)
  midpoint L30 P42
  vertical L31
  perpendicular L12 L32
  perpendicular L31 L33
  horizontal L34
  vertical L35
  horizontal L36
  vertical L37
  dimension "d281" distance P42 P43 = 0.2
  dimension "d282" distance P43 P45 = 6
  dimension "d283" distance P45 P48 = 2
extrude "Extrude1" add sketch "Sketch42" profile of A2 L12 L32 L33 L34 L36 L37 along normal blind 12
delete_face "DeleteFace1"
delete_face "DeleteFace2"
delete_face "DeleteFace3"
move_face "MoveFace3"
component_from_bodies "Body->Comp3"
sketch "Sketch43" plane through (0, 27, 0) normal (0, 1, 0) x axis (-1, 0, 0)
  line L1 (13.5, 35.9142) -> (-13.5, 35.9142)
  line L2 (23.2642, 7.15) -> (23.2642, 26.15)
  line L3 (-13.5, -2.6142) -> (13.5, -2.6142)
  line L4 (-23.2642, 26.15) -> (-23.2642, 7.15)
  line L5 (-32.7, 30) -> (-27, 33.2909)
  line L6 (-32.7, 3) -> (-32.7, 30)
  line L7 (-27, -0.2909) -> (-32.7, 3)
  line L8 (-27, -27.5) -> (-27, -0.2909)
  line L9 (15, -39.5) -> (-15, -39.5)
  line L10 (27, 34.5) -> (27, -27.5)
  line L11 (-22, 39.5) -> (22, 39.5)
  line L12 (-27, 33.2909) -> (-27, 34.5)
  line L13 (-25.5988, -29.575) -> (-23.5519, -29.575)
  line L14 (-15, -36.3) -> (-15, -38.3)
  line L15 (23.5519, -29.575) -> (25.5988, -29.575)
  line L16 (15, -38.3) -> (15, -36.3)
  line L17 (22, 36.3) -> (22, 38.3)
  line L18 (25.8, 34.5) -> (23.8, 34.5)
  line L19 (-22, 38.3) -> (-22, 36.3)
  line L20 (-23.8, 34.5) -> (-25.8, 34.5)
  line L21 (-22, 34.5) -> (-27, 34.5)
  line L22 (-22, 39.5) -> (-22, 34.5)
  line L23 (-27, 39.5) -> (-22, 39.5)
  line L24 (-27, 34.5) -> (-27, 39.5)
  line L25 (-23, 34.5) -> (-22, 34.5)
  line L26 (-23, 35.5) -> (-23, 34.5)
  line L27 (-22, 35.5) -> (-23, 35.5)
  line L28 (-22, 34.5) -> (-22, 35.5)
  arc A1 centre (13.5, 26.15) radius 9.7642 clockwise from (13.5, 35.9142) to (23.2642, 26.15)
  arc A2 centre (13.5, 7.15) radius 9.7642 clockwise from (23.2642, 7.15) to (13.5, -2.6142)
  arc A3 centre (-13.5, 7.15) radius 9.7642 clockwise from (-13.5, -2.6142) to (-23.2642, 7.15)
  arc A4 centre (-13.5, 26.15) radius 9.7642 clockwise from (-23.2642, 26.15) to (-13.5, 35.9142)
  arc A5 centre (-15, -27.5) radius 12 clockwise from (-15, -39.5) to (-27, -27.5)
  arc A6 centre (15, -27.5) radius 12 clockwise from (27, -27.5) to (15, -39.5)
  arc A7 centre (22, 34.5) radius 5 clockwise from (22, 39.5) to (27, 34.5)
  arc A8 centre (-22, 34.5) radius 5 clockwise from (-27, 34.5) to (-22, 39.5)
  arc A9 centre (-15, -27.5) radius 10.8 clockwise from (-15, -38.3) to (-25.5988, -29.575)
  arc A10 centre (-15, -27.5) radius 8.8 clockwise from (-15, -36.3) to (-23.5519, -29.575)
  arc A11 centre (15, -27.5) radius 8.8 clockwise from (23.5519, -29.575) to (15, -36.3)
  arc A12 centre (15, -27.5) radius 10.8 clockwise from (25.5988, -29.575) to (15, -38.3)
  arc A13 centre (22, 34.5) radius 3.8 clockwise from (22, 38.3) to (25.8, 34.5)
  arc A14 centre (22, 34.5) radius 1.8 clockwise from (22, 36.3) to (23.8, 34.5)
  arc A15 centre (-22, 34.5) radius 3.8 clockwise from (-25.8, 34.5) to (-22, 38.3)
  arc A16 centre (-22, 34.5) radius 3.8 clockwise from (-25.8, 34.5) to (-22, 38.3)
  arc A17 centre (-22, 34.5) radius 1.8 clockwise from (-23.8, 34.5) to (-22, 36.3)
  circle C1 centre (-23, 35.5) radius 2.3858
  circle C2 centre (-23, 35.5) radius 0.9
  point P27 (-22, 39.5)
  point P55 (-22, 39.5)
  point P28 (-27, 34.5)
  point P53 (-27, 34.5)
  point P47 (-22, 34.5)
  point P57 (-22, 34.5)
  point P59 (-23, 35.5)
  point P61 (-23, 35.5)
  point P58 (-23, 34.5)
  point P60 (-22, 35.5)
  horizontal L21
  vertical L22
  horizontal L23
  vertical L24
  coincident P27 P55
  coincident P28 P53
  horizontal L25
  vertical L26
  horizontal L27
  vertical L28
  coincident P47 P57
  coincident P59 P61
  tangent A16 C1
  concentric C1 C2
  dimension "d286" distance P57 P58 = 1
  dimension "d287" distance P57 P60 = 1
  dimension "d288" diameter C2 = 1.8
extrude "Extrude55" new body sketch "Sketch43" profile of L19 L20 A17 C1 C2 against normal blind 27.2 and against normal blind 2
sketch "Sketch44" plane through (0, 25, 0) normal (0, 1, 0) x axis (-1, 0, 0)
  line L1 (-20.6142, 35.5) -> (-23, 35.5)
  line L2 (-23, 33.1142) -> (-23, 35.5)
  line L3 (-30.2484, 33.1142) -> (-23, 33.1142)
  line L4 (-28.2117, 33.1142) -> (-23, 33.1142)
  line L5 (-28.2117, 40.488) -> (-28.2117, 33.1142)
  line L6 (-23, 40.488) -> (-28.2117, 40.488)
  line L7 (-23, 33.1142) -> (-23, 40.488)
  line L8 (-27.5483, 35.5) -> (-20.6142, 35.5)
  line L9 (-27.5483, 39.7628) -> (-27.5483, 35.5)
  line L10 (-20.6142, 39.7628) -> (-27.5483, 39.7628)
  line L11 (-20.6142, 35.5) -> (-20.6142, 39.7628)
  line L12 (-31.5, 26.5) -> (-32.7, 26.5)
  line L13 (-31.5, 29.3072) -> (-31.5, 26.5)
  line L14 (-27, 31.9053) -> (-31.5, 29.3072)
  line L15 (-25.8, 31.9053) -> (-27, 31.9053)
  line L16 (-25.8, 34.5) -> (-25.8, 31.9053)
  line L17 (-14.5, 38.3) -> (-22, 38.3)
  line L18 (-14.5, 39.5) -> (-14.5, 38.3)
  line L19 (-22, 39.5) -> (-14.5, 39.5)
  line L20 (-27, 33.2909) -> (-27, 34.5)
  line L21 (-32.7, 30) -> (-27, 33.2909)
  line L22 (-32.7, 26.5) -> (-32.7, 30)
  circle C1 centre (-23, 35.5) radius 0.9
  circle C2 centre (-23, 35.5) radius 2.3858
  circle C3 centre (-23, 35.5) radius 0.9
  arc A1 centre (-22, 34.5) radius 3.8 clockwise from (-25.8, 34.5) to (-22, 38.3)
  arc A2 centre (-22, 34.5) radius 5 clockwise from (-27, 34.5) to (-22, 39.5)
  point P3 (-23, 35.5)
  point P4 (-23, 35.5)
  point P5 (-20.6142, 35.5)
  point P6 (-23, 35.5)
  point P7 (-23, 33.1142)
  coincident P3 P4
  coincident C2 P5
  horizontal L1
  coincident P3 P6
  coincident C2 P7
  perpendicular L1 L2
  tangent C2 L3
  horizontal L4
  vertical L5
  horizontal L6
  vertical L7
  horizontal L8
  vertical L9
  horizontal L10
  vertical L11
extrude "Extrude56" new body sketch "Sketch44" profile of C2 L3 L4 L7 L8 L11 L16 A1 L17 against normal blind 23.7
combine "Combine21"
mirror "Mirror4" mirrorStitchTolerance 0.1
move "Move7"
mirror "Mirror5" mirrorStitchTolerance 0.1
mirror "Mirror6" mirrorStitchTolerance 0.1
combine "Combine1"
offset_faces "OffsetFaces1" distance 1.5
delete_face "DeleteFace4"
delete_face "DeleteFace5"
delete_face "DeleteFace6"
delete_face "DeleteFace7"
delete_face "DeleteFace8"
offset_faces "OffsetFaces2" distance 1.5
delete_face "DeleteFace9"
delete_face "DeleteFace10"
delete_face "DeleteFace11"
delete_face "DeleteFace12"
sketch "Sketch1" plane through (0, 25, 0) normal (0, -1, 0) x axis (1, 0, 0)
  line L1 (21.9401, 7.15) -> (21.9401, 26.15)
  line L2 (-13.5, -1.2901) -> (13.5, -1.2901)
  line L3 (-21.9401, 26.15) -> (-21.9401, 7.15)
  line L4 (13.5, 34.5901) -> (-13.5, 34.5901)
  line L5 (24.1, 34.5) -> (24.1, -27.5)
  line L6 (20, 36.6) -> (22, 36.6)
  line L7 (20, 38.1) -> (20, 36.6)
  line L8 (22, 38.1) -> (20, 38.1)
  line L9 (25.6, 31.7053) -> (25.6, 34.5)
  line L10 (26.9464, 31.7053) -> (25.6, 31.7053)
  line L11 (31.3, 29.1917) -> (26.9464, 31.7053)
  line L12 (31.3, 26.3) -> (31.3, 29.1917)
  line L13 (32.7, 26.3) -> (31.3, 26.3)
  line L14 (32.7, 30) -> (32.7, 26.3)
  line L15 (27, 33.2909) -> (32.7, 30)
  line L16 (27, 34.5) -> (27, 33.2909)
  line L17 (14.5, 39.5) -> (22, 39.5)
  line L18 (14.5, 36.6) -> (14.5, 39.5)
  line L19 (-6.5, 36.6) -> (14.5, 36.6)
  line L20 (-6.5, 39.5) -> (-6.5, 36.6)
  line L21 (-22, 39.5) -> (-6.5, 39.5)
  line L22 (-27, -27.5) -> (-27, 34.5)
  line L23 (15, -39.5) -> (-15, -39.5)
  line L24 (27, -0.2909) -> (27, -27.5)
  line L25 (32.7, 3) -> (27, -0.2909)
  line L26 (32.7, 6.7) -> (32.7, 3)
  line L27 (31.3, 6.7) -> (32.7, 6.7)
  line L28 (31.3, 3.8083) -> (31.3, 6.7)
  line L29 (26.9464, 1.2947) -> (31.3, 3.8083)
  line L30 (25.6, 1.2947) -> (26.9464, 1.2947)
  line L31 (25.6, -27.5) -> (25.6, 1.2947)
  line L32 (-15, -38.1) -> (15, -38.1)
  line L33 (-25.6, 34.5) -> (-25.6, -27.5)
  line L34 (-20, 38.1) -> (-22, 38.1)
  line L35 (-20, 36.6) -> (-20, 38.1)
  line L36 (-22, 36.6) -> (-20, 36.6)
  line L37 (-24.1, -27.5) -> (-24.1, 34.5)
  line L38 (15, -36.6) -> (-15, -36.6)
  line L39 (31.5, 26.5) -> (32.7, 26.5)
  line L40 (31.5, 29.3072) -> (31.5, 26.5)
  line L41 (27, 31.9053) -> (31.5, 29.3072)
  line L42 (25.8, 31.9053) -> (27, 31.9053)
  line L43 (25.8, 33.1142) -> (25.8, 31.9053)
  line L44 (23, 33.1142) -> (25.8, 33.1142)
  line L45 (20.6142, 38.3) -> (20.6142, 35.5)
  line L46 (14.5, 38.3) -> (20.6142, 38.3)
  line L47 (14.5, 39.5) -> (14.5, 38.3)
  line L48 (22, 39.5) -> (14.5, 39.5)
  line L49 (27, 33.2909) -> (27, 34.5)
  line L50 (32.7, 30) -> (27, 33.2909)
  line L51 (32.7, 26.5) -> (32.7, 30)
  line L52 (18.1142, -33.5) -> (18.1142, -37.8413)
  line L53 (25.1773, -31.1142) -> (20.5, -31.1142)
  line L54 (25.8, 1.0947) -> (25.8, -27.5)
  line L55 (27, 1.0947) -> (25.8, 1.0947)
  line L56 (31.5, 3.6928) -> (27, 1.0947)
  line L57 (31.5, 6.5) -> (31.5, 3.6928)
  line L58 (32.7, 6.5) -> (31.5, 6.5)
  line L59 (32.7, 3) -> (32.7, 6.5)
  line L60 (27, -0.2909) -> (32.7, 3)
  line L61 (27, -27.5) -> (27, -0.2909)
  line L62 (-15, -39.5) -> (15, -39.5)
  line L63 (-27, 34.5) -> (-27, -27.5)
  line L64 (-6.5, 39.5) -> (-22, 39.5)
  line L65 (-6.5, 38.3) -> (-6.5, 39.5)
  line L66 (-20.6142, 38.3) -> (-6.5, 38.3)
  line L67 (-20.6142, 35.5) -> (-20.6142, 38.3)
  line L68 (-25.8, 33.1142) -> (-23, 33.1142)
  line L69 (-25.8, -27.5) -> (-25.8, 33.1142)
  line L70 (-20.5, -31.1142) -> (-25.1773, -31.1142)
  line L71 (-18.1142, -37.8413) -> (-18.1142, -33.5)
  line L72 (15, -38.3) -> (-15, -38.3)
  line L73 (14.2, 39.8) -> (14.2, 38)
  line L74 (22, 39.8) -> (14.2, 39.8)
  line L75 (27.3, 33.4641) -> (27.3, 34.5)
  line L76 (33, 30.1732) -> (27.3, 33.4641)
  line L77 (33, 26.2) -> (33, 30.1732)
  line L78 (31.2, 26.2) -> (33, 26.2)
  line L79 (31.2, 29.134) -> (31.2, 26.2)
  line L80 (26.9196, 31.6053) -> (31.2, 29.134)
  line L81 (25.5, 31.6053) -> (26.9196, 31.6053)
  line L82 (25.5, 32.8142) -> (25.5, 31.6053)
  line L83 (23, 32.8142) -> (25.5, 32.8142)
  line L84 (20.3142, 38) -> (20.3142, 35.5)
  line L85 (14.2, 38) -> (20.3142, 38)
  line L86 (25.6, 30.2053) -> (24.1, 30.2053)
  line L87 (25.6, 34.5) -> (25.6, 30.2053)
  line L88 (20, 38.1) -> (22, 38.1)
  line L89 (20, 36.6) -> (20, 38.1)
  line L90 (22, 36.6) -> (20, 36.6)
  line L91 (24.1, 30.2053) -> (24.1, 34.5)
  line L92 (-20.3142, 35.5) -> (-20.3142, 38)
  line L93 (-20.3142, 38) -> (-6.2, 38)
  line L94 (-6.2, 38) -> (-6.2, 39.8)
  line L95 (-6.2, 39.8) -> (-22, 39.8)
  line L96 (-27.3, 34.5) -> (-27.3, -27.5)
  line L97 (-15, -39.8) -> (15, -39.8)
  line L98 (27.3, -27.5) -> (27.3, -0.4641)
  line L99 (27.3, -0.4641) -> (33, 2.8268)
  line L100 (33, 2.8268) -> (33, 6.8)
  line L101 (33, 6.8) -> (31.2, 6.8)
  line L102 (31.2, 6.8) -> (31.2, 3.866)
  line L103 (31.2, 3.866) -> (26.9196, 1.3947)
  line L104 (26.9196, 1.3947) -> (25.5, 1.3947)
  line L105 (25.5, 1.3947) -> (25.5, -27.5)
  line L106 (24.9632, -30.8142) -> (20.5, -30.8142)
  line L107 (17.8142, -33.5) -> (17.8142, -37.6158)
  line L108 (15, -38) -> (-15, -38)
  line L109 (-17.8142, -37.6158) -> (-17.8142, -33.5)
  line L110 (-20.5, -30.8142) -> (-24.9632, -30.8142)
  line L111 (-25.5, -27.5) -> (-25.5, 32.8142)
  line L112 (-25.5, 32.8142) -> (-23, 32.8142)
  line L113 (-25.6, -27.5) -> (-25.6, 34.5)
  line L114 (15, -38.1) -> (-15, -38.1)
  line L115 (25.6, 2.7947) -> (25.6, -27.5)
  line L116 (24.1, 2.7947) -> (25.6, 2.7947)
  line L117 (24.1, -27.5) -> (24.1, 2.7947)
  line L118 (-15, -36.6) -> (15, -36.6)
  line L119 (-24.1, 34.5) -> (-24.1, -27.5)
  line L120 (-20, 36.6) -> (-22, 36.6)
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  dimension "d303" = -0.3
  dimension "d304" = -0.3
extrude "Extrude1" cut sketch "Sketch1" along normal blind 7
sketch "Sketch45" plane through (0, 5.3, 0) normal (0, 1, 0) x axis (-1, 0, 0)
  line L1 (12, 23.1343) -> (12, 22.7)
  line L2 (6, 23.15) -> (11.75, 23.15)
  line L3 (6, 22.65) -> (6, 23.15)
  line L4 (4, 22.65) -> (6, 22.65)
  line L5 (4, 23.15) -> (4, 22.65)
  line L6 (-4, 23.15) -> (4, 23.15)
  line L7 (-4, 22.65) -> (-4, 23.15)
  line L8 (-6, 22.65) -> (-4, 22.65)
  line L9 (-6, 23.15) -> (-6, 22.65)
  line L10 (-11.75, 23.15) -> (-6, 23.15)
  line L11 (-13.75, -5.575) -> (-13.75, 21.15)
  line L12 (-13.25, -5.575) -> (-13.75, -5.575)
  line L13 (-13.25, -7.575) -> (-13.25, -5.575)
  line L14 (-13.75, -7.575) -> (-13.25, -7.575)
  line L15 (-13.75, -27.575) -> (-13.75, -7.575)
  line L16 (-13.25, -27.575) -> (-13.75, -27.575)
  line L17 (-13.25, -29.575) -> (-13.25, -27.575)
  line L18 (-13.75, -29.575) -> (-13.25, -29.575)
  line L19 (-13.75, -37.15) -> (-13.75, -29.575)
  line L20 (13.3863, -38.3) -> (-13.3863, -38.3)
  line L21 (13.75, -29.575) -> (13.75, -37.15)
  line L22 (13.25, -29.575) -> (13.75, -29.575)
  line L23 (13.25, -27.575) -> (13.25, -29.575)
  line L24 (13.75, -27.575) -> (13.25, -27.575)
  line L25 (13.75, -7.575) -> (13.75, -27.575)
  line L26 (13.25, -7.575) -> (13.75, -7.575)
  line L27 (13.25, -5.575) -> (13.25, -7.575)
  line L28 (13.75, -5.575) -> (13.25, -5.575)
  line L29 (13.75, 14.425) -> (13.75, -5.575)
  line L30 (13.25, 14.425) -> (13.75, 14.425)
  line L31 (13.25, 16.425) -> (13.25, 14.425)
  line L32 (13.75, 16.425) -> (13.25, 16.425)
  line L33 (13.75, 21.15) -> (13.75, 16.425)
  line L34 (12, 22.7) -> (13.0139, 22.7)
  line L35 (8.25, -22.575) -> (8.25, -33.3)
  line L36 (8.75, -22.575) -> (8.25, -22.575)
  line L37 (8.75, -12.575) -> (8.75, -22.575)
  line L38 (8.25, -12.575) -> (8.75, -12.575)
  line L39 (8.25, -0.575) -> (8.25, -12.575)
  line L40 (8.75, -0.575) -> (8.25, -0.575)
  line L41 (8.75, 9.425) -> (8.75, -0.575)
  line L42 (8.25, 9.425) -> (8.75, 9.425)
  line L43 (8.25, 17.65) -> (8.25, 9.425)
  line L44 (1, 17.65) -> (8.25, 17.65)
  line L45 (-1, 17.65) -> (1, 17.65)
  line L46 (-8.75, 17.65) -> (-1, 17.65)
  line L47 (-8.75, -0.575) -> (-8.75, 17.65)
  line L48 (-8.25, -0.575) -> (-8.75, -0.575)
  line L49 (-8.25, -12.575) -> (-8.25, -0.575)
  line L50 (-8.75, -12.575) -> (-8.25, -12.575)
  line L51 (-8.75, -22.575) -> (-8.75, -12.575)
  line L52 (-8.25, -22.575) -> (-8.75, -22.575)
  line L53 (-8.25, -33.3) -> (-8.25, -22.575)
  line L54 (8.25, -33.3) -> (-8.25, -33.3)
  line L55 (-8.75, -33.3) -> (8.25, -33.3)
  line L56 (-8.75, 17.65) -> (-8.75, -33.3)
  line L57 (8.25, 17.65) -> (-8.75, 17.65)
  line L58 (8.25, -33.3) -> (8.25, 17.65)
  arc A1 centre (11.75, 21.15) radius 2 clockwise from (11.75, 23.15) to (12, 23.1343)
  arc A2 centre (-11.75, 21.15) radius 2 clockwise from (-13.75, 21.15) to (-11.75, 23.15)
  arc A3 centre (-11.75, -37.15) radius 2 clockwise from (-13.3863, -38.3) to (-13.75, -37.15)
  arc A4 centre (11.75, -37.15) radius 2 clockwise from (13.75, -37.15) to (13.3863, -38.3)
  arc A5 centre (11.75, 21.15) radius 2 clockwise from (13.0139, 22.7) to (13.75, 21.15)
  horizontal L55
  vertical L56
  horizontal L57
  vertical L58
  dimension "d307" = -5
extrude "Extrude2" cut sketch "Sketch45" profile of L35 L45 L39 L51 L43 L46 L47 L48 L49 L50 L52 L53 L54 L55 L56 L57 L58 against normal blind 4
extrude "Extrude2" cut of existing geometry blind -2.609
move_face "MoveFace1"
